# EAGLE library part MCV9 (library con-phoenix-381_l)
Mini-Combicon 3.81mm vertikal 9polig (ohne Gegenstecker)
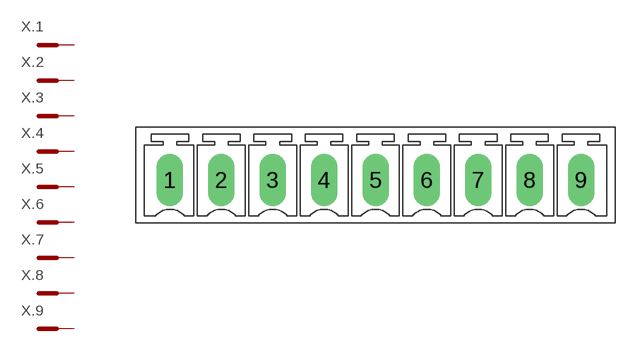
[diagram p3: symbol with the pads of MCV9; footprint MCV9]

Designator prefix X; gates .1=MCST .2=MCST .3=MCST .4=MCST .5=MCST .6=MCST .7=MCST .8=MCST .9=MCST

## MCV9  [MCV9]
1  .1:SK  pas
2  .2:SK  pas
3  .3:SK  pas
4  .4:SK  pas
5  .5:SK  pas
6  .6:SK  pas
7  .7:SK  pas
8  .8:SK  pas
9  .9:SK  pas

## Footprint MCV9 (pad centres in mm)
Mini-Combicon 3.81mm vertikal 9-polig (ohne Gegenstecker)
drill 1.3 pad 1.905 long: 1 -15.24,0; 2 -11.43,0; 3 -7.62,0; 4 -3.81,0; 5 0,0; 6 3.81,0; 7 7.62,0; 8 11.43,0; 9 15.24,0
